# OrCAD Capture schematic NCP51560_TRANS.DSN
size B; title: NCP51560 4.5A/9A, 5kVrms Isolated Dual Channel Gate Driver; rev: 0
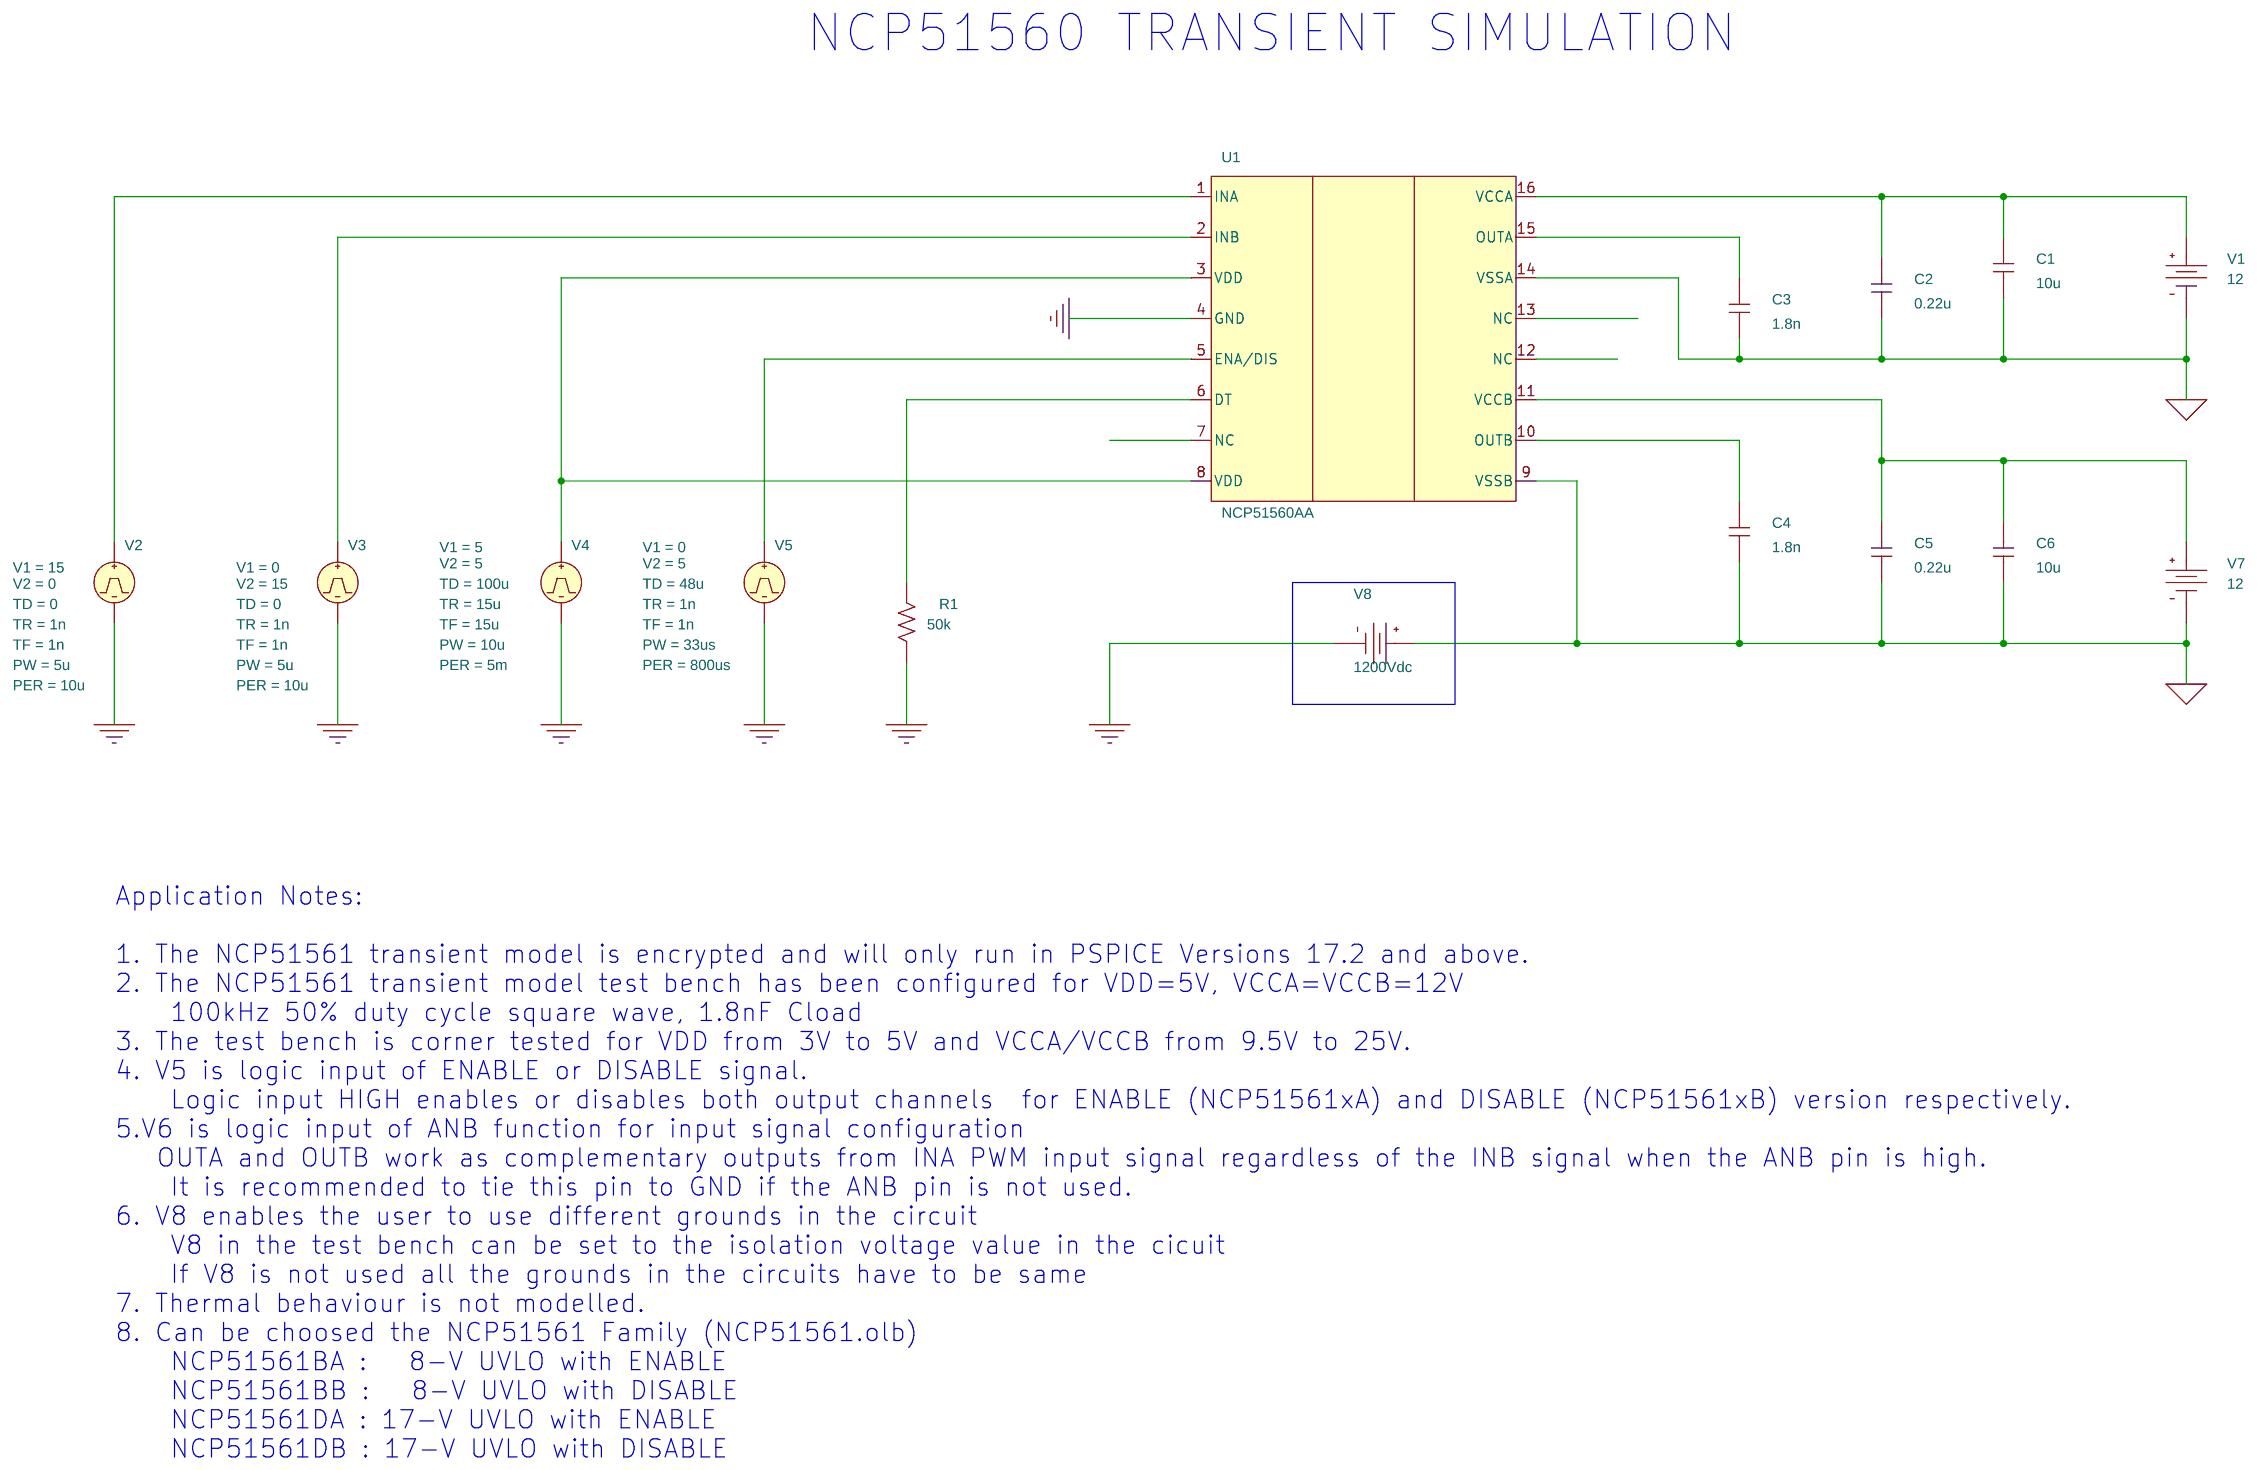
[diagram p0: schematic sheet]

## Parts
C1  10u  [RAD/CK05]
C2  0.22u  [RAD/CK05]
C3  1.8n  [RAD/CK05]
C4  1.8n  [RAD/CK05]
C5  0.22u  [RAD/CK05]
C6  10u  [RAD/CK05]
R1  50k  [AX/RC05]
U1  NCP51560AA
V1  VDC
V2  VPULSE
V3  VPULSE
V4  VPULSE
V5  VPULSE
V7  VDC
V8  VDC

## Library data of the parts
C1-C6 = C
R1 = R
U1 = NCP51560AA
V1 V7 = VDC: DC: 12
V2 = VPULSE: PER: 10u; PW: 5u; TD: 0; TF: 1n; TR: 1n; V1: 15; V2: 0
V3 = VPULSE: PER: 10u; PW: 5u; TD: 0; TF: 1n; TR: 1n; V1: 0; V2: 15
V4 = VPULSE: PER: 5m; PW: 10u; TD: 100u; TF: 15u; TR: 15u; V1: 5; V2: 5
V5 = VPULSE: PER: 800us; PW: 33us; TD: 48u; TF: 1n; TR: 1n; V1: 0; V2: 5
V8 = VDC: DC: 1200Vdc

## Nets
GND_SIGNAL: C1.2 C2.2 C3.1 C4.1 C5.2 C6.2 U1.9(VSSB) U1.14(VSSA) V1.1(-) V7.1(-) V8.0(+)
0: R1.1 U1.4(GND) V2.2(-) V3.2(-) V4.2(-) V5.2(-) V8.1(-)
N16734273: U1.1(INA) V2.1(+)
N16734289: C1.1 C2.1 U1.16(VCCA) V1.0(+)
N16734317: U1.2(INB) V3.1(+)
N16734391: U1.3(VDD) U1.8(VDD) V4.1(+)
N16734459: U1.5(ENA/DIS) V5.1(+)
N16734505: R1.2 U1.6(DT)
N16734547: C4.2 U1.10(OUTB)
N16734581: C5.1 C6.1 U1.11(VCCB) V7.0(+)
N16753446: C3.2 U1.15(OUTA)

Not connected (* = marked no-connect by the designer): U1 7(NC) 12(NC) 13(NC)

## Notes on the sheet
- NCP51560 TRANSIENT SIMULATION
- Application Notes:
  1. The NCP51561 transient model is encrypted and will only run in PSPICE Versions 17.2 and above.
  2. The NCP51561 transient model test bench has been configured for VDD=5V, VCCA=VCCB=12V
      100kHz 50% duty cycle square wave, 1.8nF Cload
  3. The test bench is corner tested for VDD from 3V to 5V and VCCA/VCCB from 9.5V to 25V.
  4. V5 is logic input of ENABLE or DISABLE signal.
      Logic input HIGH enables or disables both output channels  for ENABLE (NCP51561xA) and DISABLE (NCP51561xB) version respectively.
  5.V6 is logic input of ANB function for input signal configuration
     OUTA and OUTB work as complementary outputs from INA PWM input signal regardless of the INB signal when the ANB pin is high.
      It is recommended to tie this pin to GND if the ANB pin is not used.
  6. V8 enables the user to use different grounds in the circuit
      V8 in the test bench can be set to the isolation voltage value in the cicuit
      If V8 is not used all the grounds in the circuits have to be same
  7. Thermal behaviour is not modelled.
  8. Can be choosed the NCP51561 Family (NCP51561.olb)
      NCP51561BA :   8-V UVLO with ENABLE
      NCP51561BB :   8-V UVLO with DISABLE
      NCP51561DA : 17-V UVLO with ENABLE
      NCP51561DB : 17-V UVLO with DISABLE
